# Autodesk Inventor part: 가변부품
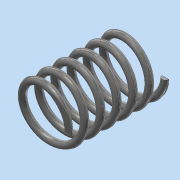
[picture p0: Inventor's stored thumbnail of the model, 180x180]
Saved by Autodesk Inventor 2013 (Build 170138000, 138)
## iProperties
Created: 2018-07
Part Number: 가변부품
Material: 스테인리스강
Document SubType Name: Modeling
Designer: dgall
Density: 8.08 g/cm^3
Mass: -0.119216 g
Surface Area: 18.9179 cm^2
Volume: -0.0147545 cm^3
Author: dgall
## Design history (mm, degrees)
sketch "스케치1"
  geometry: L1 (0, 0)-(8, 0); L2 (0, 0)-(0, 28.981); L3 (0, 28.981)-(8, 28.981); C1 r 1 at (8, 0)
  constraints: 6 end point, 2 perpendicular, 1 centre point, 1 coincident, 1 horizontal, 1 vertical alignment
  dimensions: "d0" = 28.98097 distance of L1.start L2.end (derived); "d1" = 16 diameter of L1.end L2; "d2" = 2 diameter of C1
feature "코일1" pitch "d3" = 10; turns "d5" = 6; dims "d4" = 28.98097 (= d0), "d6" = 0, angle "d7" = 90 deg, angle "d8" = 90 deg, "d9" = 0, "d10" = 0
feature "분할1"
node "작업 평면1"
feature "분할2"
node "솔리드1"
other parameters: "d11" = 0
